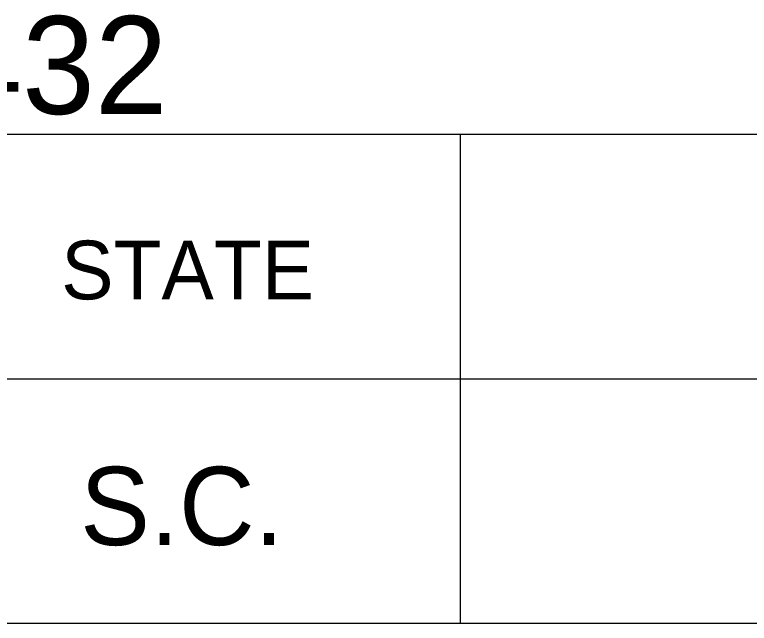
# Model space of a CAD drawing. Extents: x 1000 to 1162, y 999 to 8520.
# Drawn here: x 1136.81 to 1140.565, y 6965.046 to 6968.157 of the extents above; entities that cross this region are included whole.
import ezdxf

# ---------------------------------------------------------------- set-up
doc = ezdxf.new("R2010")
doc.units = 0
doc.layers.add('Level 20', color=7, linetype='Continuous')
doc.layers.add('Level 3', color=7, linetype='Continuous')

msp = doc.modelspace()

# ---------------------------------------------------------------- linework, layer by layer
at = {"layer": 'Level 3'}
for p, q in [((1133.055, 6967.5458), (1161.555, 6967.5458)), ((1133.055, 6967.5458), (1161.555, 6967.5458)), ((1133.055, 6967.5458), (1161.555, 6967.5458)), ((1133.055, 6967.5458), (1161.555, 6967.5458)), ((1133.055, 6967.5458), (1161.555, 6967.5458)), ((1133.055, 6967.5458), (1161.555, 6967.5458)), ((1133.055, 6967.5458), (1161.555, 6967.5458)), ((1133.055, 6967.5458), (1161.555, 6967.5458)), ((1133.055, 6967.5458), (1161.555, 6967.5458)), ((1133.055, 6967.5458), (1161.555, 6967.5458)), ((1133.055, 6967.5458), (1161.555, 6967.5458)), ((1133.055, 6967.5458), (1161.555, 6967.5458)), ((1133.055, 6967.5458), (1161.555, 6967.5458)), ((1133.055, 6967.5458), (1161.555, 6967.5458)), ((1133.055, 6967.5458), (1161.555, 6967.5458)), ((1133.055, 6967.5458), (1161.555, 6967.5458)), ((1133.055, 6967.5458), (1161.555, 6967.5458)), ((1133.055, 6967.5458), (1161.555, 6967.5458)), ((1133.055, 6967.5458), (1161.555, 6967.5458)), ((1133.055, 6967.5458), (1161.555, 6967.5458)), ((1133.055, 6967.5458), (1161.555, 6967.5458)), ((1133.055, 6967.5458), (1161.555, 6967.5458)), ((1133.055, 6967.5458), (1161.555, 6967.5458)), ((1133.055, 6967.5458), (1161.555, 6967.5458)), ((1133.055, 6967.5458), (1161.555, 6967.5458)), ((1133.055, 6967.5458), (1161.555, 6967.5458)), ((1133.055, 6967.5458), (1161.555, 6967.5458)), ((1133.055, 6967.5458), (1161.555, 6967.5458)), ((1133.055, 6967.5458), (1161.555, 6967.5458)), ((1133.055, 6967.5458), (1161.555, 6967.5458)), ((1133.055, 6967.5458), (1161.555, 6967.5458)), ((1133.055, 6967.5458), (1161.555, 6967.5458)), ((1133.055, 6967.5458), (1161.555, 6967.5458)), ((1133.055, 6967.5458), (1161.555, 6967.5458)), ((1133.055, 6967.5458), (1161.555, 6967.5458)), ((1133.055, 6967.5458), (1161.555, 6967.5458)), ((1133.055, 6967.5458), (1161.555, 6967.5458)), ((1133.055, 6967.5458), (1161.555, 6967.5458)), ((1133.055, 6967.5458), (1161.555, 6967.5458)), ((1133.055, 6967.5458), (1161.555, 6967.5458)), ((1133.055, 6967.5458), (1161.555, 6967.5458)), ((1133.055, 6967.5458), (1161.555, 6967.5458)), ((1133.055, 6967.5458), (1161.555, 6967.5458)), ((1133.055, 6967.5458), (1161.555, 6967.5458)), ((1133.055, 6967.5458), (1161.555, 6967.5458)), ((1133.055, 6967.5458), (1161.555, 6967.5458)), ((1133.055, 6967.5458), (1161.555, 6967.5458)), ((1133.055, 6967.5458), (1161.555, 6967.5458)), ((1133.055, 6967.5458), (1161.555, 6967.5458)), ((1133.055, 6967.5458), (1161.555, 6967.5458)), ((1139.0868, 6967.5458), (1139.0868, 6965.0458)), ((1139.0868, 6967.5458), (1139.0868, 6965.0458)), ((1139.0868, 6967.5458), (1139.0868, 6965.0458)), ((1139.0868, 6967.5458), (1139.0868, 6965.0458)), ((1139.0868, 6967.5458), (1139.0868, 6965.0458)), ((1139.0868, 6967.5458), (1139.0868, 6965.0458)), ((1139.0868, 6967.5458), (1139.0868, 6965.0458)), ((1139.0868, 6967.5458), (1139.0868, 6965.0458)), ((1139.0868, 6967.5458), (1139.0868, 6965.0458)), ((1139.0868, 6967.5458), (1139.0868, 6965.0458)), ((1139.0868, 6967.5458), (1139.0868, 6965.0458)), ((1139.0868, 6967.5458), (1139.0868, 6965.0458)), ((1139.0868, 6967.5458), (1139.0868, 6965.0458)), ((1139.0868, 6967.5458), (1139.0868, 6965.0458)), ((1139.0868, 6967.5458), (1139.0868, 6965.0458)), ((1139.0868, 6967.5458), (1139.0868, 6965.0458)), ((1139.0868, 6967.5458), (1139.0868, 6965.0458)), ((1139.0868, 6967.5458), (1139.0868, 6965.0458)), ((1139.0868, 6967.5458), (1139.0868, 6965.0458)), ((1139.0868, 6967.5458), (1139.0868, 6965.0458)), ((1139.0868, 6967.5458), (1139.0868, 6965.0458)), ((1139.0868, 6967.5458), (1139.0868, 6965.0458)), ((1139.0868, 6967.5458), (1139.0868, 6965.0458)), ((1139.0868, 6967.5458), (1139.0868, 6965.0458)), ((1139.0868, 6967.5458), (1139.0868, 6965.0458)), ((1139.0868, 6967.5458), (1139.0868, 6965.0458)), ((1139.0868, 6967.5458), (1139.0868, 6965.0458)), ((1139.0868, 6967.5458), (1139.0868, 6965.0458)), ((1139.0868, 6967.5458), (1139.0868, 6965.0458)), ((1139.0868, 6967.5458), (1139.0868, 6965.0458)), ((1139.0868, 6967.5458), (1139.0868, 6965.0458)), ((1139.0868, 6967.5458), (1139.0868, 6965.0458)), ((1139.0868, 6967.5458), (1139.0868, 6965.0458)), ((1139.0868, 6967.5458), (1139.0868, 6965.0458)), ((1139.0868, 6967.5458), (1139.0868, 6965.0458)), ((1139.0868, 6967.5458), (1139.0868, 6965.0458)), ((1139.0868, 6967.5458), (1139.0868, 6965.0458)), ((1139.0868, 6967.5458), (1139.0868, 6965.0458)), ((1139.0868, 6967.5458), (1139.0868, 6965.0458)), ((1139.0868, 6967.5458), (1139.0868, 6965.0458)), ((1139.0868, 6967.5458), (1139.0868, 6965.0458)), ((1139.0868, 6967.5458), (1139.0868, 6965.0458)), ((1139.0868, 6967.5458), (1139.0868, 6965.0458)), ((1139.0868, 6967.5458), (1139.0868, 6965.0458)), ((1139.0868, 6967.5458), (1139.0868, 6965.0458)), ((1139.0868, 6967.5458), (1139.0868, 6965.0458)), ((1139.0868, 6967.5458), (1139.0868, 6965.0458)), ((1139.0868, 6967.5458), (1139.0868, 6965.0458)), ((1139.0868, 6967.5458), (1139.0868, 6965.0458)), ((1139.0868, 6967.5458), (1139.0868, 6965.0458)), ((1133.055, 6966.2958), (1161.555, 6966.2958)), ((1133.055, 6966.2958), (1161.555, 6966.2958)), ((1133.055, 6966.2958), (1161.555, 6966.2958)), ((1133.055, 6966.2958), (1161.555, 6966.2958)), ((1133.055, 6966.2958), (1161.555, 6966.2958)), ((1133.055, 6966.2958), (1161.555, 6966.2958)), ((1133.055, 6966.2958), (1161.555, 6966.2958)), ((1133.055, 6966.2958), (1161.555, 6966.2958)), ((1133.055, 6966.2958), (1161.555, 6966.2958)), ((1133.055, 6966.2958), (1161.555, 6966.2958)), ((1133.055, 6966.2958), (1161.555, 6966.2958)), ((1133.055, 6966.2958), (1161.555, 6966.2958)), ((1133.055, 6966.2958), (1161.555, 6966.2958)), ((1133.055, 6966.2958), (1161.555, 6966.2958)), ((1133.055, 6966.2958), (1161.555, 6966.2958)), ((1133.055, 6966.2958), (1161.555, 6966.2958)), ((1133.055, 6966.2958), (1161.555, 6966.2958)), ((1133.055, 6966.2958), (1161.555, 6966.2958)), ((1133.055, 6966.2958), (1161.555, 6966.2958)), ((1133.055, 6966.2958), (1161.555, 6966.2958)), ((1133.055, 6966.2958), (1161.555, 6966.2958)), ((1133.055, 6966.2958), (1161.555, 6966.2958)), ((1133.055, 6966.2958), (1161.555, 6966.2958)), ((1133.055, 6966.2958), (1161.555, 6966.2958)), ((1133.055, 6966.2958), (1161.555, 6966.2958)), ((1133.055, 6966.2958), (1161.555, 6966.2958)), ((1133.055, 6966.2958), (1161.555, 6966.2958)), ((1133.055, 6966.2958), (1161.555, 6966.2958)), ((1133.055, 6966.2958), (1161.555, 6966.2958)), ((1133.055, 6966.2958), (1161.555, 6966.2958)), ((1133.055, 6966.2958), (1161.555, 6966.2958)), ((1133.055, 6966.2958), (1161.555, 6966.2958)), ((1133.055, 6966.2958), (1161.555, 6966.2958)), ((1133.055, 6966.2958), (1161.555, 6966.2958)), ((1133.055, 6966.2958), (1161.555, 6966.2958)), ((1133.055, 6966.2958), (1161.555, 6966.2958)), ((1133.055, 6966.2958), (1161.555, 6966.2958)), ((1133.055, 6966.2958), (1161.555, 6966.2958)), ((1133.055, 6966.2958), (1161.555, 6966.2958)), ((1133.055, 6966.2958), (1161.555, 6966.2958)), ((1133.055, 6966.2958), (1161.555, 6966.2958)), ((1133.055, 6966.2958), (1161.555, 6966.2958)), ((1133.055, 6966.2958), (1161.555, 6966.2958)), ((1133.055, 6966.2958), (1161.555, 6966.2958)), ((1133.055, 6966.2958), (1161.555, 6966.2958)), ((1133.055, 6966.2958), (1161.555, 6966.2958)), ((1133.055, 6966.2958), (1161.555, 6966.2958)), ((1133.055, 6966.2958), (1161.555, 6966.2958)), ((1133.055, 6966.2958), (1161.555, 6966.2958)), ((1133.055, 6966.2958), (1161.555, 6966.2958)), ((1133.055, 6965.0458), (1161.555, 6965.0458)), ((1133.055, 6965.0458), (1161.555, 6965.0458)), ((1133.055, 6965.0458), (1161.555, 6965.0458)), ((1133.055, 6965.0458), (1161.555, 6965.0458)), ((1133.055, 6965.0458), (1161.555, 6965.0458)), ((1133.055, 6965.0458), (1161.555, 6965.0458)), ((1133.055, 6965.0458), (1161.555, 6965.0458)), ((1133.055, 6965.0458), (1161.555, 6965.0458)), ((1133.055, 6965.0458), (1161.555, 6965.0458)), ((1133.055, 6965.0458), (1161.555, 6965.0458)), ((1133.055, 6965.0458), (1161.555, 6965.0458)), ((1133.055, 6965.0458), (1161.555, 6965.0458)), ((1133.055, 6965.0458), (1161.555, 6965.0458)), ((1133.055, 6965.0458), (1161.555, 6965.0458)), ((1133.055, 6965.0458), (1161.555, 6965.0458)), ((1133.055, 6965.0458), (1161.555, 6965.0458)), ((1133.055, 6965.0458), (1161.555, 6965.0458)), ((1133.055, 6965.0458), (1161.555, 6965.0458)), ((1133.055, 6965.0458), (1161.555, 6965.0458)), ((1133.055, 6965.0458), (1161.555, 6965.0458)), ((1133.055, 6965.0458), (1161.555, 6965.0458)), ((1133.055, 6965.0458), (1161.555, 6965.0458)), ((1133.055, 6965.0458), (1161.555, 6965.0458)), ((1133.055, 6965.0458), (1161.555, 6965.0458)), ((1133.055, 6965.0458), (1161.555, 6965.0458)), ((1133.055, 6965.0458), (1161.555, 6965.0458)), ((1133.055, 6965.0458), (1161.555, 6965.0458)), ((1133.055, 6965.0458), (1161.555, 6965.0458)), ((1133.055, 6965.0458), (1161.555, 6965.0458)), ((1133.055, 6965.0458), (1161.555, 6965.0458)), ((1133.055, 6965.0458), (1161.555, 6965.0458)), ((1133.055, 6965.0458), (1161.555, 6965.0458)), ((1133.055, 6965.0458), (1161.555, 6965.0458)), ((1133.055, 6965.0458), (1161.555, 6965.0458)), ((1133.055, 6965.0458), (1161.555, 6965.0458)), ((1133.055, 6965.0458), (1161.555, 6965.0458)), ((1133.055, 6965.0458), (1161.555, 6965.0458)), ((1133.055, 6965.0458), (1161.555, 6965.0458)), ((1133.055, 6965.0458), (1161.555, 6965.0458)), ((1133.055, 6965.0458), (1161.555, 6965.0458)), ((1133.055, 6965.0458), (1161.555, 6965.0458)), ((1133.055, 6965.0458), (1161.555, 6965.0458)), ((1133.055, 6965.0458), (1161.555, 6965.0458)), ((1133.055, 6965.0458), (1161.555, 6965.0458)), ((1133.055, 6965.0458), (1161.555, 6965.0458)), ((1133.055, 6965.0458), (1161.555, 6965.0458)), ((1133.055, 6965.0458), (1161.555, 6965.0458)), ((1133.055, 6965.0458), (1161.555, 6965.0458)), ((1133.055, 6965.0458), (1161.555, 6965.0458)), ((1133.055, 6965.0458), (1161.555, 6965.0458))]:
    msp.add_line(p, q, dxfattribs=at)

# ---------------------------------------------------------------- texts
at = {"layer": 'Level 20'}
msp.add_text('PIN NO. 26432', height=0.5, dxfattribs=at).set_placement((1133.0578, 6967.65))
at = {"layer": 'Level 3'}
for s, height, p in [('STATE', 0.3, (1137.0478, 6966.7021)), ('STATE', 0.3, (1137.0478, 6966.7021)), ('STATE', 0.3, (1137.0478, 6966.7021)), ('STATE', 0.3, (1137.0478, 6966.7021)), ('STATE', 0.3, (1137.0478, 6966.7021)), ('STATE', 0.3, (1137.0478, 6966.7021)), ('STATE', 0.3, (1137.0478, 6966.7021)), ('STATE', 0.3, (1137.0478, 6966.7021)), ('STATE', 0.3, (1137.0478, 6966.7021)), ('STATE', 0.3, (1137.0478, 6966.7021)), ('STATE', 0.3, (1137.0478, 6966.7021)), ('STATE', 0.3, (1137.0478, 6966.7021)), ('STATE', 0.3, (1137.0478, 6966.7021)), ('STATE', 0.3, (1137.0478, 6966.7021)), ('STATE', 0.3, (1137.0478, 6966.7021)), ('STATE', 0.3, (1137.0478, 6966.7021)), ('STATE', 0.3, (1137.0478, 6966.7021)), ('STATE', 0.3, (1137.0478, 6966.7021)), ('STATE', 0.3, (1137.0478, 6966.7021)), ('STATE', 0.3, (1137.0478, 6966.7021)), ('STATE', 0.3, (1137.0478, 6966.7021)), ('STATE', 0.3, (1137.0478, 6966.7021)), ('STATE', 0.3, (1137.0478, 6966.7021)), ('STATE', 0.3, (1137.0478, 6966.7021)), ('STATE', 0.3, (1137.0478, 6966.7021)), ('STATE', 0.3, (1137.0478, 6966.7021)), ('STATE', 0.3, (1137.0478, 6966.7021)), ('STATE', 0.3, (1137.0478, 6966.7021)), ('STATE', 0.3, (1137.0478, 6966.7021)), ('STATE', 0.3, (1137.0478, 6966.7021)), ('STATE', 0.3, (1137.0478, 6966.7021)), ('STATE', 0.3, (1137.0478, 6966.7021)), ('STATE', 0.3, (1137.0478, 6966.7021)), ('STATE', 0.3, (1137.0478, 6966.7021)), ('STATE', 0.3, (1137.0478, 6966.7021)), ('STATE', 0.3, (1137.0478, 6966.7021)), ('STATE', 0.3, (1137.0478, 6966.7021)), ('STATE', 0.3, (1137.0478, 6966.7021)), ('STATE', 0.3, (1137.0478, 6966.7021)), ('STATE', 0.3, (1137.0478, 6966.7021)), ('STATE', 0.3, (1137.0478, 6966.7021)), ('STATE', 0.3, (1137.0478, 6966.7021)), ('STATE', 0.3, (1137.0478, 6966.7021)), ('STATE', 0.3, (1137.0478, 6966.7021)), ('STATE', 0.3, (1137.0478, 6966.7021)), ('STATE', 0.3, (1137.0478, 6966.7021)), ('STATE', 0.3, (1137.0478, 6966.7021)), ('STATE', 0.3, (1137.0478, 6966.7021)), ('STATE', 0.3, (1137.0478, 6966.7021)), ('STATE', 0.3, (1137.0478, 6966.7021)), ('S.C.', 0.39999, (1137.1448, 6965.4458)), ('S.C.', 0.39999, (1137.1448, 6965.4458)), ('S.C.', 0.39999, (1137.1448, 6965.4458)), ('S.C.', 0.39999, (1137.1448, 6965.4458)), ('S.C.', 0.39999, (1137.1448, 6965.4458)), ('S.C.', 0.39999, (1137.1448, 6965.4458)), ('S.C.', 0.39999, (1137.1448, 6965.4458)), ('S.C.', 0.39999, (1137.1448, 6965.4458)), ('S.C.', 0.39999, (1137.1448, 6965.4458)), ('S.C.', 0.39999, (1137.1448, 6965.4458)), ('S.C.', 0.39999, (1137.1448, 6965.4458)), ('S.C.', 0.39999, (1137.1448, 6965.4458)), ('S.C.', 0.39999, (1137.1448, 6965.4458)), ('S.C.', 0.39999, (1137.1448, 6965.4458)), ('S.C.', 0.39999, (1137.1448, 6965.4458)), ('S.C.', 0.39999, (1137.1448, 6965.4458)), ('S.C.', 0.39999, (1137.1448, 6965.4458)), ('S.C.', 0.39999, (1137.1448, 6965.4458)), ('S.C.', 0.39999, (1137.1448, 6965.4458)), ('S.C.', 0.39999, (1137.1448, 6965.4458)), ('S.C.', 0.39999, (1137.1448, 6965.4458)), ('S.C.', 0.39999, (1137.1448, 6965.4458)), ('S.C.', 0.39999, (1137.1448, 6965.4458)), ('S.C.', 0.39999, (1137.1448, 6965.4458)), ('S.C.', 0.39999, (1137.1448, 6965.4458)), ('S.C.', 0.39999, (1137.1448, 6965.4458)), ('S.C.', 0.39999, (1137.1448, 6965.4458)), ('S.C.', 0.39999, (1137.1448, 6965.4458)), ('S.C.', 0.39999, (1137.1448, 6965.4458)), ('S.C.', 0.39999, (1137.1448, 6965.4458)), ('S.C.', 0.39999, (1137.1448, 6965.4458)), ('S.C.', 0.39999, (1137.1448, 6965.4458)), ('S.C.', 0.39999, (1137.1448, 6965.4458)), ('S.C.', 0.39999, (1137.1448, 6965.4458)), ('S.C.', 0.39999, (1137.1448, 6965.4458)), ('S.C.', 0.39999, (1137.1448, 6965.4458)), ('S.C.', 0.39999, (1137.1448, 6965.4458)), ('S.C.', 0.39999, (1137.1448, 6965.4458)), ('S.C.', 0.39999, (1137.1448, 6965.4458)), ('S.C.', 0.39999, (1137.1448, 6965.4458)), ('S.C.', 0.39999, (1137.1448, 6965.4458)), ('S.C.', 0.39999, (1137.1448, 6965.4458)), ('S.C.', 0.39999, (1137.1448, 6965.4458)), ('S.C.', 0.39999, (1137.1448, 6965.4458)), ('S.C.', 0.39999, (1137.1448, 6965.4458)), ('S.C.', 0.39999, (1137.1448, 6965.4458)), ('S.C.', 0.39999, (1137.1448, 6965.4458)), ('S.C.', 0.39999, (1137.1448, 6965.4458)), ('S.C.', 0.39999, (1137.1448, 6965.4458)), ('S.C.', 0.39999, (1137.1448, 6965.4458))]:
    msp.add_text(s, height=height, dxfattribs=at).set_placement(p)

doc.saveas('drawing.dxf')
